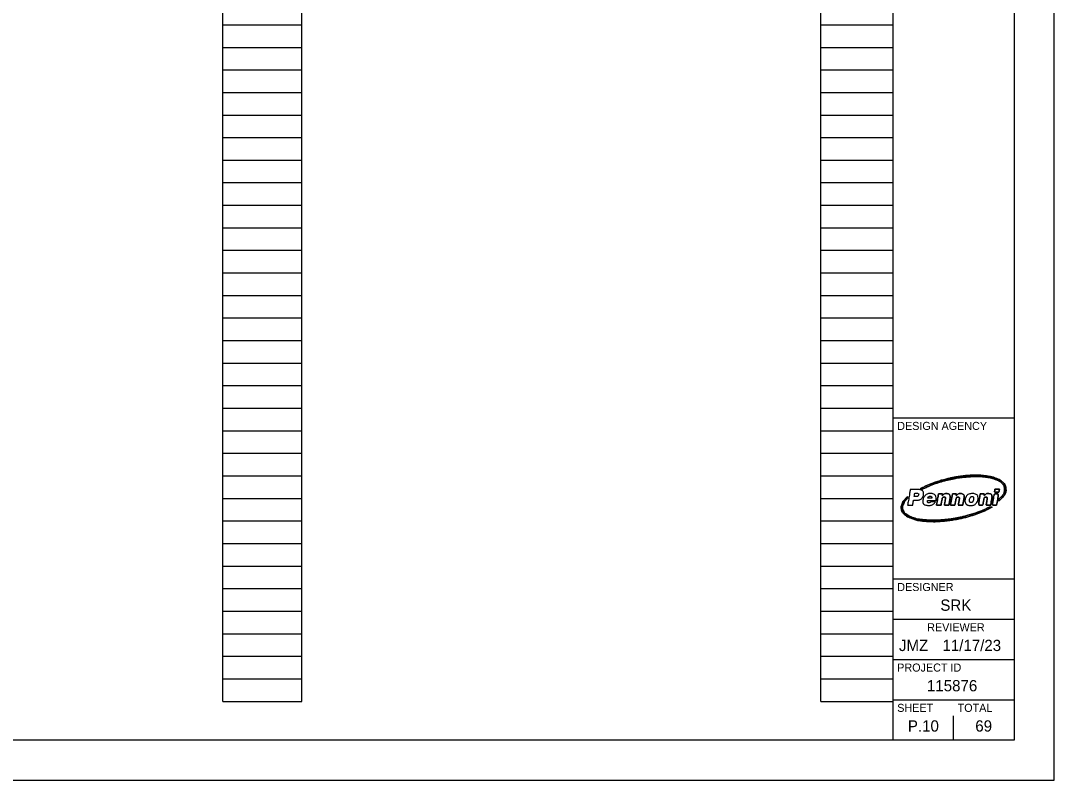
# Model space of a CAD drawing. Extents: x -16.1 to 34, y 0 to 22.
# Drawn here: x 21.17 to 34, y 0 to 9.43 of the extents above; entities that cross this region are included whole.
import ezdxf

# ---------------------------------------------------------------- set-up
doc = ezdxf.new("R2010")
doc.units = 0
for name, color, linetype in [('SH_Border', 7, 'Continuous'), ('SH_Cut_Line', 7, 'Continuous'), ('SH_Data', 7, 'Continuous')]:
    doc.layers.add(name, color=color, linetype=linetype)

msp = doc.modelspace()

# ---------------------------------------------------------------- linework, layer by layer
at = {"layer": 'SH_Border'}
for p, q in [((32, 0.5), (32, 21.5)), ((32, 4.5), (33.5, 4.5)), ((32.48, 3.503), (32.43, 3.503)), ((32, 2.5), (33.5, 2.5)), ((32, 2), (33.5, 2)), ((32, 1.5), (33.5, 1.5)), ((32, 1), (33.5, 1))]:
    msp.add_line(p, q, dxfattribs=at)
msp.add_lwpolyline([(1.5, 21.5), (33.5, 21.5), (33.5, 0.5), (1.5, 0.5)], close=True, dxfattribs=at)
for points, degree in [([(32.339, 3.621), (32.346, 3.619), (32.352, 3.616), (32.358, 3.615), (32.36, 3.614), (32.363, 3.614), (32.365, 3.615), (32.393, 3.629), (32.422, 3.643), (32.451, 3.655), (32.492, 3.673), (32.534, 3.688), (32.577, 3.701), (32.619, 3.714), (32.662, 3.725), (32.705, 3.734), (32.745, 3.743), (32.785, 3.751), (32.825, 3.756), (32.857, 3.76), (32.889, 3.764), (32.921, 3.767), (32.946, 3.769), (32.972, 3.77), (32.997, 3.771), (33.052, 3.772), (33.107, 3.77), (33.161, 3.762), (33.191, 3.758), (33.22, 3.752), (33.249, 3.742), (33.284, 3.731), (33.318, 3.717), (33.346, 3.691), (33.361, 3.678), (33.373, 3.661), (33.378, 3.641), (33.383, 3.624), (33.384, 3.607), (33.381, 3.589), (33.378, 3.569), (33.368, 3.552), (33.355, 3.536), (33.343, 3.521), (33.329, 3.508), (33.315, 3.495), (33.313, 3.494), (33.312, 3.492), (33.311, 3.49), (33.31, 3.485), (33.309, 3.479), (33.308, 3.473), (33.308, 3.471), (33.307, 3.469), (33.307, 3.465), (33.331, 3.485), (33.353, 3.505), (33.372, 3.529), (33.381, 3.54), (33.389, 3.553), (33.394, 3.566), (33.401, 3.585), (33.401, 3.604), (33.399, 3.623), (33.395, 3.658), (33.379, 3.685), (33.353, 3.708), (33.329, 3.728), (33.301, 3.741), (33.272, 3.752), (33.235, 3.766), (33.197, 3.774), (33.157, 3.779), (33.122, 3.784), (33.087, 3.787), (33.052, 3.788), (32.996, 3.789), (32.939, 3.787), (32.883, 3.781), (32.852, 3.777), (32.822, 3.773), (32.791, 3.768), (32.746, 3.761), (32.701, 3.752), (32.656, 3.74), (32.596, 3.725), (32.536, 3.707), (32.478, 3.684), (32.437, 3.669), (32.397, 3.651), (32.358, 3.631), (32.352, 3.628), (32.346, 3.625), (32.339, 3.621)], 3), ([(32.339, 3.621), (32.346, 3.625), (32.352, 3.628), (32.358, 3.631), (32.397, 3.651), (32.437, 3.669), (32.478, 3.684), (32.536, 3.707), (32.596, 3.725), (32.656, 3.74), (32.701, 3.752), (32.746, 3.761), (32.791, 3.768), (32.822, 3.773), (32.852, 3.777), (32.883, 3.781), (32.939, 3.787), (32.996, 3.789), (33.052, 3.788), (33.087, 3.787), (33.122, 3.784), (33.157, 3.779), (33.197, 3.774), (33.235, 3.766), (33.272, 3.752), (33.301, 3.741), (33.329, 3.728), (33.353, 3.708), (33.379, 3.685), (33.395, 3.658), (33.399, 3.623), (33.401, 3.604), (33.401, 3.585), (33.394, 3.566), (33.389, 3.553), (33.381, 3.54), (33.372, 3.529), (33.353, 3.505), (33.331, 3.485), (33.307, 3.465), (33.307, 3.469), (33.308, 3.471), (33.308, 3.473), (33.309, 3.479), (33.31, 3.485), (33.311, 3.49), (33.312, 3.492), (33.313, 3.494), (33.315, 3.495), (33.329, 3.508), (33.343, 3.521), (33.355, 3.536), (33.368, 3.552), (33.378, 3.569), (33.381, 3.589), (33.384, 3.607), (33.383, 3.624), (33.378, 3.641), (33.373, 3.661), (33.361, 3.678), (33.346, 3.691), (33.318, 3.717), (33.284, 3.731), (33.249, 3.742), (33.22, 3.752), (33.191, 3.758), (33.161, 3.762), (33.107, 3.77), (33.052, 3.772), (32.997, 3.771), (32.972, 3.77), (32.946, 3.769), (32.921, 3.767), (32.889, 3.764), (32.857, 3.76), (32.825, 3.756), (32.785, 3.751), (32.745, 3.743), (32.705, 3.734), (32.662, 3.725), (32.619, 3.714), (32.577, 3.701), (32.534, 3.688), (32.492, 3.673), (32.451, 3.655), (32.422, 3.643), (32.393, 3.629), (32.365, 3.615), (32.363, 3.614), (32.36, 3.614), (32.358, 3.615), (32.352, 3.616), (32.346, 3.619), (32.339, 3.621)], 3), ([(32.35, 3.602), (32.338, 3.608), (32.324, 3.61), (32.311, 3.61), (32.279, 3.611), (32.247, 3.61), (32.215, 3.61), (32.213, 3.61), (32.212, 3.61), (32.212, 3.608), (32.208, 3.586), (32.204, 3.565), (32.201, 3.543), (32.195, 3.509), (32.189, 3.474), (32.183, 3.439), (32.181, 3.432), (32.18, 3.424), (32.179, 3.417)], 3), ([(32.252, 3.477), (32.26, 3.477), (32.267, 3.477), (32.273, 3.477), (32.286, 3.477), (32.299, 3.477), (32.312, 3.48), (32.329, 3.483), (32.344, 3.49), (32.356, 3.502), (32.37, 3.518), (32.377, 3.537), (32.377, 3.559), (32.377, 3.578), (32.369, 3.593), (32.35, 3.602)], 3), ([(33.319, 3.615), (33.317, 3.603), (33.315, 3.591), (33.312, 3.578), (33.312, 3.577), (33.31, 3.576), (33.309, 3.576), (33.292, 3.576), (33.275, 3.576), (33.257, 3.576), (33.258, 3.586), (33.26, 3.595), (33.261, 3.604), (33.262, 3.606), (33.263, 3.609), (33.263, 3.611), (33.263, 3.615), (33.264, 3.615), (33.268, 3.615), (33.283, 3.615), (33.299, 3.615), (33.314, 3.615), (33.316, 3.615), (33.317, 3.615), (33.319, 3.615)], 3), ([(33.319, 3.615), (33.317, 3.615), (33.316, 3.615), (33.314, 3.615), (33.299, 3.615), (33.283, 3.615), (33.268, 3.615), (33.264, 3.615), (33.263, 3.615), (33.263, 3.611), (33.263, 3.609), (33.262, 3.606), (33.261, 3.604), (33.26, 3.595), (33.258, 3.586), (33.257, 3.576), (33.275, 3.576), (33.292, 3.576), (33.309, 3.576), (33.31, 3.576), (33.312, 3.577), (33.312, 3.578), (33.315, 3.591), (33.317, 3.603), (33.319, 3.615)], 3), ([(33.227, 3.392), (33.227, 3.392), (33.227, 3.393), (33.227, 3.393), (33.217, 3.393), (33.207, 3.393), (33.197, 3.393), (33.195, 3.393), (33.192, 3.392), (33.19, 3.391), (33.152, 3.372), (33.114, 3.355), (33.075, 3.34), (33.017, 3.317), (32.958, 3.298), (32.898, 3.283), (32.855, 3.271), (32.811, 3.262), (32.768, 3.254), (32.743, 3.25), (32.718, 3.246), (32.693, 3.242), (32.668, 3.239), (32.642, 3.236), (32.616, 3.234), (32.592, 3.232), (32.568, 3.23), (32.544, 3.23), (32.516, 3.229), (32.488, 3.228), (32.459, 3.229), (32.428, 3.231), (32.397, 3.233), (32.367, 3.236), (32.328, 3.24), (32.291, 3.248), (32.254, 3.259), (32.223, 3.269), (32.193, 3.282), (32.166, 3.302), (32.149, 3.314), (32.135, 3.329), (32.126, 3.348), (32.114, 3.374), (32.115, 3.4), (32.126, 3.427), (32.135, 3.45), (32.149, 3.47), (32.166, 3.488), (32.171, 3.494), (32.177, 3.5), (32.177, 3.509), (32.177, 3.514), (32.179, 3.52), (32.18, 3.526), (32.178, 3.525), (32.178, 3.525), (32.177, 3.524), (32.168, 3.514), (32.158, 3.505), (32.149, 3.494), (32.129, 3.472), (32.113, 3.448), (32.105, 3.419), (32.1, 3.402), (32.099, 3.385), (32.102, 3.368), (32.107, 3.341), (32.121, 3.319), (32.141, 3.301), (32.164, 3.28), (32.191, 3.266), (32.219, 3.254), (32.266, 3.235), (32.315, 3.225), (32.365, 3.219), (32.396, 3.216), (32.427, 3.214), (32.458, 3.212), (32.501, 3.211), (32.543, 3.211), (32.585, 3.215), (32.619, 3.217), (32.654, 3.221), (32.688, 3.225), (32.719, 3.229), (32.749, 3.234), (32.78, 3.239), (32.834, 3.249), (32.888, 3.261), (32.941, 3.276), (32.986, 3.289), (33.031, 3.304), (33.074, 3.321), (33.117, 3.338), (33.16, 3.356), (33.2, 3.377), (33.209, 3.382), (33.218, 3.387), (33.227, 3.392)], 3), ([(33.227, 3.392), (33.218, 3.387), (33.209, 3.382), (33.2, 3.377), (33.16, 3.356), (33.117, 3.338), (33.074, 3.321), (33.031, 3.304), (32.986, 3.289), (32.941, 3.276), (32.888, 3.261), (32.834, 3.249), (32.78, 3.239), (32.749, 3.234), (32.719, 3.229), (32.688, 3.225), (32.654, 3.221), (32.619, 3.217), (32.585, 3.215), (32.543, 3.211), (32.501, 3.211), (32.458, 3.212), (32.427, 3.214), (32.396, 3.216), (32.365, 3.219), (32.315, 3.225), (32.266, 3.235), (32.219, 3.254), (32.191, 3.266), (32.164, 3.28), (32.141, 3.301), (32.121, 3.319), (32.107, 3.341), (32.102, 3.368), (32.099, 3.385), (32.1, 3.402), (32.105, 3.419), (32.113, 3.448), (32.129, 3.472), (32.149, 3.494), (32.158, 3.505), (32.168, 3.514), (32.177, 3.524), (32.178, 3.525), (32.178, 3.525), (32.18, 3.526), (32.179, 3.52), (32.177, 3.514), (32.177, 3.509), (32.177, 3.5), (32.171, 3.494), (32.166, 3.488), (32.149, 3.47), (32.135, 3.45), (32.126, 3.427), (32.115, 3.4), (32.114, 3.374), (32.126, 3.348), (32.135, 3.329), (32.149, 3.314), (32.166, 3.302), (32.193, 3.282), (32.223, 3.269), (32.254, 3.259), (32.291, 3.248), (32.328, 3.24), (32.367, 3.236), (32.397, 3.233), (32.428, 3.231), (32.459, 3.229), (32.488, 3.228), (32.516, 3.229), (32.544, 3.23), (32.568, 3.23), (32.592, 3.232), (32.616, 3.234), (32.642, 3.236), (32.668, 3.239), (32.693, 3.242), (32.718, 3.246), (32.743, 3.25), (32.768, 3.254), (32.811, 3.262), (32.855, 3.271), (32.898, 3.283), (32.958, 3.298), (33.017, 3.317), (33.075, 3.34), (33.114, 3.355), (33.152, 3.372), (33.19, 3.391), (33.192, 3.392), (33.195, 3.393), (33.197, 3.393), (33.207, 3.393), (33.217, 3.393), (33.227, 3.393), (33.227, 3.393), (33.227, 3.392), (33.227, 3.392)], 3), ([(32.179, 3.417), (32.18, 3.417), (32.18, 3.417), (32.181, 3.417), (32.2, 3.417), (32.22, 3.417), (32.239, 3.417), (32.242, 3.417), (32.242, 3.418), (32.242, 3.42), (32.244, 3.431), (32.246, 3.442), (32.248, 3.454), (32.249, 3.461), (32.251, 3.469), (32.252, 3.477)], 3), ([(32.26, 3.522), (32.262, 3.536), (32.265, 3.55), (32.267, 3.563), (32.267, 3.564), (32.269, 3.565), (32.269, 3.565), (32.281, 3.565), (32.292, 3.567), (32.304, 3.563), (32.314, 3.56), (32.318, 3.554), (32.316, 3.543)], 3), ([(32.316, 3.543), (32.313, 3.531), (32.305, 3.523), (32.292, 3.522), (32.282, 3.522), (32.271, 3.522), (32.26, 3.522)], 3), ([(32.532, 3.508), (32.528, 3.533), (32.515, 3.55), (32.491, 3.557), (32.478, 3.562), (32.464, 3.562), (32.451, 3.561), (32.429, 3.558), (32.41, 3.549), (32.394, 3.532), (32.38, 3.517), (32.372, 3.5), (32.37, 3.479), (32.367, 3.45), (32.379, 3.426), (32.408, 3.417), (32.424, 3.412), (32.44, 3.411), (32.457, 3.414), (32.474, 3.416), (32.491, 3.422), (32.504, 3.434), (32.512, 3.441), (32.519, 3.449), (32.523, 3.459)], 3), ([(32.523, 3.459), (32.506, 3.459), (32.489, 3.459), (32.472, 3.458), (32.471, 3.458), (32.47, 3.457), (32.469, 3.457), (32.465, 3.454), (32.461, 3.45), (32.456, 3.448), (32.44, 3.442), (32.423, 3.451), (32.424, 3.47), (32.424, 3.474), (32.425, 3.475), (32.429, 3.475), (32.461, 3.475), (32.493, 3.475), (32.525, 3.475), (32.527, 3.475), (32.529, 3.475), (32.531, 3.475)], 3), ([(32.43, 3.503), (32.431, 3.515), (32.44, 3.525), (32.453, 3.527), (32.459, 3.528), (32.465, 3.528), (32.47, 3.525), (32.478, 3.521), (32.481, 3.513), (32.48, 3.503)], 3), ([(32.531, 3.475), (32.533, 3.486), (32.533, 3.497), (32.532, 3.508)], 2), ([(32.538, 3.416), (32.538, 3.415), (32.539, 3.415), (32.539, 3.415), (32.556, 3.415), (32.573, 3.415), (32.59, 3.415), (32.593, 3.415), (32.593, 3.416), (32.594, 3.418), (32.595, 3.426), (32.596, 3.435), (32.598, 3.443), (32.601, 3.46), (32.604, 3.478), (32.608, 3.495), (32.609, 3.505), (32.614, 3.513), (32.624, 3.515), (32.637, 3.519), (32.651, 3.516), (32.648, 3.497), (32.647, 3.482), (32.644, 3.468), (32.642, 3.454), (32.64, 3.441), (32.637, 3.428), (32.635, 3.416), (32.636, 3.415), (32.636, 3.415), (32.637, 3.415), (32.654, 3.415), (32.671, 3.415), (32.688, 3.415), (32.69, 3.415), (32.691, 3.416), (32.691, 3.419), (32.695, 3.442), (32.699, 3.466), (32.704, 3.49), (32.706, 3.502), (32.708, 3.515), (32.706, 3.527), (32.704, 3.543), (32.695, 3.554), (32.679, 3.558), (32.657, 3.564), (32.638, 3.56), (32.62, 3.545), (32.617, 3.542), (32.613, 3.538), (32.609, 3.535), (32.61, 3.542), (32.612, 3.549), (32.613, 3.557), (32.596, 3.557), (32.58, 3.557), (32.564, 3.556), (32.563, 3.556), (32.562, 3.555), (32.562, 3.554), (32.561, 3.55), (32.56, 3.545), (32.559, 3.541), (32.554, 3.511), (32.549, 3.48), (32.543, 3.45), (32.541, 3.438), (32.539, 3.427), (32.538, 3.416)], 3), ([(32.538, 3.416), (32.539, 3.427), (32.541, 3.438), (32.543, 3.45), (32.549, 3.48), (32.554, 3.511), (32.559, 3.541), (32.56, 3.545), (32.561, 3.55), (32.562, 3.554), (32.562, 3.555), (32.563, 3.556), (32.564, 3.556), (32.58, 3.557), (32.596, 3.557), (32.613, 3.557), (32.612, 3.549), (32.61, 3.542), (32.609, 3.535), (32.613, 3.538), (32.617, 3.542), (32.62, 3.545), (32.638, 3.56), (32.657, 3.564), (32.679, 3.558), (32.695, 3.554), (32.704, 3.543), (32.706, 3.527), (32.708, 3.515), (32.706, 3.502), (32.704, 3.49), (32.699, 3.466), (32.695, 3.442), (32.691, 3.419), (32.691, 3.416), (32.69, 3.415), (32.688, 3.415), (32.671, 3.415), (32.654, 3.415), (32.637, 3.415), (32.636, 3.415), (32.636, 3.415), (32.635, 3.416), (32.637, 3.428), (32.64, 3.441), (32.642, 3.454), (32.644, 3.468), (32.647, 3.482), (32.648, 3.497), (32.651, 3.516), (32.637, 3.519), (32.624, 3.515), (32.614, 3.513), (32.609, 3.505), (32.608, 3.495), (32.604, 3.478), (32.601, 3.46), (32.598, 3.443), (32.596, 3.435), (32.595, 3.426), (32.594, 3.418), (32.593, 3.416), (32.593, 3.415), (32.59, 3.415), (32.573, 3.415), (32.556, 3.415), (32.539, 3.415), (32.539, 3.415), (32.538, 3.415), (32.538, 3.416)], 3), ([(32.711, 3.416), (32.711, 3.415), (32.711, 3.415), (32.711, 3.415), (32.729, 3.415), (32.746, 3.415), (32.764, 3.415), (32.765, 3.415), (32.766, 3.417), (32.766, 3.418), (32.769, 3.435), (32.772, 3.452), (32.775, 3.469), (32.777, 3.479), (32.779, 3.49), (32.782, 3.5), (32.786, 3.513), (32.798, 3.519), (32.811, 3.516), (32.817, 3.515), (32.82, 3.511), (32.821, 3.505), (32.822, 3.502), (32.822, 3.499), (32.822, 3.496), (32.82, 3.485), (32.818, 3.473), (32.816, 3.462), (32.813, 3.447), (32.811, 3.431), (32.808, 3.416), (32.808, 3.415), (32.808, 3.415), (32.809, 3.415), (32.826, 3.415), (32.844, 3.415), (32.861, 3.415), (32.862, 3.415), (32.864, 3.417), (32.864, 3.418), (32.868, 3.441), (32.872, 3.463), (32.876, 3.485), (32.878, 3.497), (32.88, 3.509), (32.88, 3.522), (32.88, 3.537), (32.874, 3.55), (32.858, 3.556), (32.838, 3.564), (32.818, 3.562), (32.8, 3.55), (32.794, 3.545), (32.788, 3.54), (32.782, 3.535), (32.783, 3.543), (32.785, 3.549), (32.786, 3.557), (32.769, 3.557), (32.753, 3.557), (32.738, 3.557), (32.735, 3.557), (32.735, 3.555), (32.735, 3.553), (32.73, 3.529), (32.726, 3.505), (32.722, 3.481), (32.718, 3.46), (32.714, 3.438), (32.711, 3.416)], 3), ([(32.711, 3.416), (32.714, 3.438), (32.718, 3.46), (32.722, 3.481), (32.726, 3.505), (32.73, 3.529), (32.735, 3.553), (32.735, 3.555), (32.735, 3.557), (32.738, 3.557), (32.753, 3.557), (32.769, 3.557), (32.786, 3.557), (32.785, 3.549), (32.783, 3.543), (32.782, 3.535), (32.788, 3.54), (32.794, 3.545), (32.8, 3.55), (32.818, 3.562), (32.838, 3.564), (32.858, 3.556), (32.874, 3.55), (32.88, 3.537), (32.88, 3.522), (32.88, 3.509), (32.878, 3.497), (32.876, 3.485), (32.872, 3.463), (32.868, 3.441), (32.864, 3.418), (32.864, 3.417), (32.862, 3.415), (32.861, 3.415), (32.844, 3.415), (32.826, 3.415), (32.809, 3.415), (32.808, 3.415), (32.808, 3.415), (32.808, 3.416), (32.811, 3.431), (32.813, 3.447), (32.816, 3.462), (32.818, 3.473), (32.82, 3.485), (32.822, 3.496), (32.822, 3.499), (32.822, 3.502), (32.821, 3.505), (32.82, 3.511), (32.817, 3.515), (32.811, 3.516), (32.798, 3.519), (32.786, 3.513), (32.782, 3.5), (32.779, 3.49), (32.777, 3.479), (32.775, 3.469), (32.772, 3.452), (32.769, 3.435), (32.766, 3.418), (32.766, 3.417), (32.765, 3.415), (32.764, 3.415), (32.746, 3.415), (32.729, 3.415), (32.711, 3.415), (32.711, 3.415), (32.711, 3.415), (32.711, 3.416)], 3), ([(33.053, 3.508), (33.052, 3.53), (33.041, 3.545), (33.021, 3.554), (33.001, 3.562), (32.982, 3.562), (32.962, 3.558), (32.938, 3.553), (32.918, 3.541), (32.905, 3.52), (32.904, 3.518), (32.903, 3.515), (32.902, 3.513), (32.901, 3.511), (32.899, 3.509), (32.899, 3.507), (32.894, 3.496), (32.891, 3.484), (32.891, 3.472), (32.891, 3.47), (32.891, 3.467), (32.891, 3.465), (32.891, 3.457), (32.893, 3.45), (32.895, 3.444), (32.896, 3.443), (32.897, 3.441), (32.897, 3.44), (32.898, 3.439), (32.898, 3.438), (32.899, 3.437), (32.901, 3.434), (32.904, 3.43), (32.908, 3.427), (32.909, 3.426), (32.911, 3.424), (32.914, 3.423), (32.914, 3.422), (32.915, 3.422), (32.915, 3.422), (32.917, 3.421), (32.918, 3.42), (32.919, 3.42), (32.921, 3.419), (32.923, 3.418), (32.925, 3.417), (32.936, 3.412), (32.947, 3.411), (32.959, 3.41)], 3), ([(32.946, 3.471), (32.947, 3.487), (32.95, 3.501), (32.959, 3.513), (32.964, 3.519), (32.971, 3.523), (32.979, 3.523), (32.988, 3.523), (32.994, 3.52), (32.996, 3.511), (32.997, 3.505), (32.998, 3.498), (32.997, 3.491)], 3), ([(32.997, 3.491), (32.997, 3.481), (32.994, 3.471), (32.989, 3.462), (32.983, 3.452), (32.973, 3.447), (32.962, 3.449), (32.956, 3.45), (32.951, 3.453), (32.949, 3.459), (32.948, 3.464), (32.947, 3.469), (32.946, 3.471)], 3), ([(32.959, 3.41), (32.966, 3.411), (32.974, 3.412), (32.981, 3.413), (33, 3.416), (33.017, 3.425), (33.03, 3.439), (33.047, 3.459), (33.055, 3.482), (33.053, 3.508)], 3), ([(33.081, 3.556), (33.073, 3.509), (33.065, 3.462), (33.057, 3.415), (33.076, 3.415), (33.094, 3.415), (33.112, 3.415), (33.115, 3.43), (33.117, 3.444), (33.12, 3.458), (33.122, 3.471), (33.124, 3.484), (33.127, 3.496), (33.13, 3.51), (33.14, 3.517), (33.153, 3.517), (33.162, 3.516), (33.167, 3.511), (33.168, 3.503), (33.168, 3.5), (33.168, 3.497), (33.168, 3.494), (33.164, 3.475), (33.161, 3.456), (33.158, 3.437), (33.156, 3.43), (33.155, 3.423), (33.154, 3.415), (33.173, 3.415), (33.191, 3.415), (33.209, 3.415), (33.21, 3.417), (33.21, 3.418), (33.21, 3.419), (33.214, 3.44), (33.218, 3.462), (33.221, 3.483), (33.224, 3.497), (33.227, 3.51), (33.226, 3.525), (33.224, 3.541), (33.216, 3.553), (33.2, 3.558), (33.175, 3.565), (33.153, 3.559), (33.135, 3.541), (33.133, 3.539), (33.131, 3.537), (33.129, 3.535), (33.129, 3.535), (33.129, 3.535), (33.128, 3.536), (33.129, 3.542), (33.131, 3.549), (33.132, 3.556), (33.115, 3.556), (33.098, 3.556), (33.081, 3.556)], 3), ([(33.081, 3.556), (33.098, 3.556), (33.115, 3.556), (33.132, 3.556), (33.131, 3.549), (33.129, 3.542), (33.128, 3.536), (33.129, 3.535), (33.129, 3.535), (33.129, 3.535), (33.131, 3.537), (33.133, 3.539), (33.135, 3.541), (33.153, 3.559), (33.175, 3.565), (33.2, 3.558), (33.216, 3.553), (33.224, 3.541), (33.226, 3.525), (33.227, 3.51), (33.224, 3.497), (33.221, 3.483), (33.218, 3.462), (33.214, 3.44), (33.21, 3.419), (33.21, 3.418), (33.21, 3.417), (33.209, 3.415), (33.191, 3.415), (33.173, 3.415), (33.154, 3.415), (33.155, 3.423), (33.156, 3.43), (33.158, 3.437), (33.161, 3.456), (33.164, 3.475), (33.168, 3.494), (33.168, 3.497), (33.168, 3.5), (33.168, 3.503), (33.167, 3.511), (33.162, 3.516), (33.153, 3.517), (33.14, 3.517), (33.13, 3.51), (33.127, 3.496), (33.124, 3.484), (33.122, 3.471), (33.12, 3.458), (33.117, 3.444), (33.115, 3.43), (33.112, 3.415), (33.094, 3.415), (33.076, 3.415), (33.057, 3.415), (33.065, 3.462), (33.073, 3.509), (33.081, 3.556)], 3), ([(33.284, 3.417), (33.266, 3.417), (33.247, 3.417), (33.229, 3.417), (33.237, 3.464), (33.245, 3.51), (33.253, 3.557), (33.272, 3.557), (33.29, 3.557), (33.309, 3.557), (33.3, 3.51), (33.292, 3.464), (33.284, 3.417)], 3), ([(33.284, 3.417), (33.292, 3.464), (33.3, 3.51), (33.309, 3.557), (33.29, 3.557), (33.272, 3.557), (33.253, 3.557), (33.245, 3.51), (33.237, 3.464), (33.229, 3.417), (33.247, 3.417), (33.266, 3.417), (33.284, 3.417)], 3)]:
    msp.add_open_spline(points, degree=degree, dxfattribs=at)
at = {"layer": 'SH_Cut_Line'}
msp.add_lwpolyline([(0, 0), (34, 0), (34, 22), (0, 22)], close=True, dxfattribs=at)
at = {"layer": 'SH_Data'}
for p, q in [((23.68, 0.98), (23.68, 21.14)), ((24.66, 0.98), (24.66, 21.14)), ((31.1, 0.98), (31.1, 21.14)), ((32, 0.98), (32, 21.14)), ((23.68, 9.38), (24.66, 9.38)), ((31.1, 9.38), (32, 9.38)), ((23.68, 9.1), (24.66, 9.1)), ((31.1, 9.1), (32, 9.1)), ((23.68, 8.82), (24.66, 8.82)), ((31.1, 8.82), (32, 8.82)), ((23.68, 8.54), (24.66, 8.54)), ((31.1, 8.54), (32, 8.54)), ((23.68, 8.26), (24.66, 8.26)), ((31.1, 8.26), (32, 8.26)), ((23.68, 7.98), (24.66, 7.98)), ((31.1, 7.98), (32, 7.98)), ((23.68, 7.7), (24.66, 7.7)), ((31.1, 7.7), (32, 7.7)), ((23.68, 7.42), (24.66, 7.42)), ((31.1, 7.42), (32, 7.42)), ((23.68, 7.14), (24.66, 7.14)), ((31.1, 7.14), (32, 7.14)), ((23.68, 6.86), (24.66, 6.86)), ((31.1, 6.86), (32, 6.86)), ((23.68, 6.58), (24.66, 6.58)), ((31.1, 6.58), (32, 6.58)), ((23.68, 6.3), (24.66, 6.3)), ((31.1, 6.3), (32, 6.3)), ((23.68, 6.02), (24.66, 6.02)), ((31.1, 6.02), (32, 6.02)), ((23.68, 5.74), (24.66, 5.74)), ((31.1, 5.74), (32, 5.74)), ((23.68, 5.46), (24.66, 5.46)), ((31.1, 5.46), (32, 5.46)), ((23.68, 5.18), (24.66, 5.18)), ((31.1, 5.18), (32, 5.18)), ((23.68, 4.9), (24.66, 4.9)), ((31.1, 4.9), (32, 4.9)), ((23.68, 4.62), (24.66, 4.62)), ((31.1, 4.62), (32, 4.62)), ((23.68, 4.34), (24.66, 4.34)), ((31.1, 4.34), (32, 4.34)), ((23.68, 4.06), (24.66, 4.06)), ((31.1, 4.06), (32, 4.06)), ((23.68, 3.78), (24.66, 3.78)), ((31.1, 3.78), (32, 3.78)), ((23.68, 3.5), (24.66, 3.5)), ((31.1, 3.5), (32, 3.5)), ((32.75, 3.5), (32.75, 3.5)), ((23.68, 3.22), (24.66, 3.22)), ((31.1, 3.22), (32, 3.22)), ((23.68, 2.94), (24.66, 2.94)), ((31.1, 2.94), (32, 2.94)), ((23.68, 2.66), (24.66, 2.66)), ((31.1, 2.66), (32, 2.66)), ((23.68, 2.38), (24.66, 2.38)), ((31.1, 2.38), (32, 2.38)), ((23.68, 2.1), (24.66, 2.1)), ((31.1, 2.1), (32, 2.1)), ((23.68, 1.82), (24.66, 1.82)), ((31.1, 1.82), (32, 1.82)), ((23.68, 1.54), (24.66, 1.54)), ((31.1, 1.54), (32, 1.54)), ((23.68, 1.26), (24.66, 1.26)), ((31.1, 1.26), (32, 1.26)), ((23.68, 0.98), (24.66, 0.98)), ((31.1, 0.98), (32, 0.98)), ((32.75, 0.5), (32.75, 0.8)), ((32.375, 0.675), (32.375, 0.675))]:
    msp.add_line(p, q, dxfattribs=at)

# ---------------------------------------------------------------- texts
for s, height, p in [('DESIGN AGENCY', 0.1, (32.05, 4.35)), ('DESIGNER', 0.1, (32.05, 2.35)), ('SRK', 0.14, (32.585, 2.105)), ('REVIEWER', 0.1, (32.422, 1.85)), ('JMZ', 0.14, (32.071, 1.605)), ('11/17/23', 0.14, (32.611, 1.605)), ('PROJECT ID', 0.1, (32.05, 1.35)), ('115876', 0.14, (32.419, 1.105)), ('SHEET', 0.1, (32.05, 0.85)), ('TOTAL', 0.1, (32.8, 0.85)), ('P.10', 0.14, (32.182, 0.605)), ('69', 0.14, (33.019, 0.605))]:
    msp.add_text(s, height=height, dxfattribs=at).set_placement(p)

doc.saveas('drawing.dxf')
